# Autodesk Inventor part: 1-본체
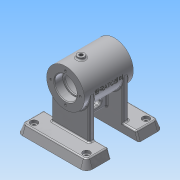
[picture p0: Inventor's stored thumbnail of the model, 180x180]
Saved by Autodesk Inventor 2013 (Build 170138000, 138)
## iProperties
Created: 2016-07
Part Number: 1-본체
Material: 알루미늄 6061
Document SubType Name: Modeling
Designer: Administrator
Density: 2.71 g/cm^3
Mass: 500.735 g
Surface Area: 535.201 cm^2
Volume: 184.773 cm^3
Author: Administrator
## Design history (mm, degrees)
sketch "스케치1"
  geometry: C1 r 27 at (0, 70); 1 further point
  constraints: 1 centre point, 1 vertical alignment
  dimensions: "d0" = 54 diameter of C1; "d1" = 70 distance of point (0, 0) C1.centre
extrude "돌출1" new body sketch "스케치1" stored distance "d2" = 70; taper "d3" = 0 deg
node "작업 평면1"
sketch "스케치2"
  geometry: L1 (-50, 0)-(50, 0); L2 (-45.632, 12)-(45.632, 12); L3 (50, 0)-(45.632, 12); L4 (-50, 0)-(-45.632, 12); 2 further points
  constraints: 8 end point, 2 horizontal alignment, 1 horizontal, 1 midpoint, 1 parallel
  dimensions: "d5" = 100 distance of L1.start L1.end; "d7" = 50 distance of point (0, 0) L1.start; "d8" = 12 distance between parallel lines of L1 L2; "d9" = 70 deg angle of L1 L3; "d11" = 70 deg angle of L1 L4
extrude "돌출2" join sketch "스케치2" distance "d12" = 35; taper "d13" = 0 deg
feature "면 기울기2" dims angle "d17" = 20 deg
fillet "모깎기2" dims "d18" = 5, "d19" = 10
fillet "모깎기3" dims "d20" = 10, "d21" = 5
sketch "스케치3"
  geometry: L1 (95.632, -12)-(4.368, -12) reference; L2 (23, -12)-(23, -70); L3 (77, -12)-(77, -70); L4 (8.59, -12)-(91.41, -12) reference; L5 (23, -70)-(77, -70); L6 (77, -12)-(23, -12); A1 r 27 centre (50, -70) between (23, -70) and (77, -70) reference; 1 further point
  constraints: 8 end point, 2 point on circle, 2 point on line, 1 parallel, 1 perpendicular
  dimensions: "d22" = 27 distance from line of point (50, 0) L2; "d23" = 27 distance from line of point (50, 0) L3
extrude "돌출3" join sketch "스케치3" distance "d24" = 8; taper "d25" = 0 deg
sketch "스케치5"
  geometry: L1 (-22, 22)-(-22, 62); L2 (-22, 62)-(22, 62); L3 (22, 62)-(22, 22); L4 (22, 22)-(-22, 22); L5 (-35, 43)-(35, 43) reference; 1 further point
  constraints: 8 end point, 2 parallel, 1 perpendicular, 1 vertical
  dimensions: "d29" = 21 distance between parallel lines of L4 L5; "d30" = 40 distance between parallel lines of L2 L4; "d31" = 22 distance from line of L3 point (0, 0); "d32" = 22 distance from line of point (0, 0) L1
extrude "돌출4" join sketch "스케치5" stored distance "d33" = 8; taper "d34" = 0 deg
sketch "스케치6"
  geometry: L1 (-22, -20)-(-22, 20) reference; L2 (-35.5, 8)-(-35.5, -8); L3 (-28.5, 8)-(-28.5, -8); A1 r 3.5 centre (-32, 8) between (-35.5, 8) and (-28.5, 8); A2 r 3.5 centre (-32, -8) between (-35.5, -8) and (-28.5, -8); 1 further point
  constraints: 4 end point, 4 point on circle, 2 centre point, 2 tangent, 1 parallel, 1 vertical alignment
  dimensions: "d35" = 7 diameter of A1; "d36" = 7 diameter of A2; "d37" = 16 distance of A2.centre A1.centre; "d38" = 32 horizontal distance of A2.centre point (0, 0); "d39" = 8 vertical distance of point (0, 0) A1.centre; "d40" = 16 distance of L3.start L3.end
extrude "돌출5" cut sketch "스케치6" distance "d41" = 20; taper "d42" = 0 deg
node "작업 평면2"
sketch "스케치7"
  geometry: L1 (-27, -35)-(27, -35) reference; C1 r 5 at (0, -13); 1 further point
  constraints: 1 centre point, 1 vertical alignment
  dimensions: "d44" = 10 diameter of C1; "d45" = 22 distance from line of C1.centre L1
extrude "돌출6" join sketch "스케치7" distance "d46" = 20; taper "d47" = 0 deg
sketch "스케치8"
  geometry: L1 (-47.948, 70)-(56.24, 70); L2 (50, 0)-(-50, 0) reference; L3 (0, 70)-(15.898, 44.559); 2 further points
  constraints: 4 end point, 1 horizontal, 1 midpoint, 1 point on line, 1 vertical alignment
  dimensions: "d48" = 70 distance between parallel lines of L2 L1; "d49" = 30 distance of L3.start L3.end; "d50" = 58 deg angle of L1 L3
node "작업 평면3"
sketch "스케치9"
  geometry: C1 r 6 at (0, 0); 2 further points
  constraints: 1 centre point, 1 coincident
  dimensions: "d51" = 12 diameter of C1
extrude "돌출7" join sketch "스케치9" distance "d53" = 20; taper "d54" = 0 deg
sketch "스케치10"
  geometry: C1 r 27 at (0, 0) reference; C2 r 16 at (0, 0); 1 further point
  constraints: 1 centre point, 1 coincident
  dimensions: "d55" = 32 diameter of C2
extrude "돌출8" cut sketch "스케치10" distance "d56" = 12; taper "d57" = 0 deg
sketch "스케치11"
  geometry: C1 r 16 at (0, 0) reference; C2 r 14 at (0, 0); 1 further point
  constraints: 1 centre point, 1 coincident
  dimensions: "d58" = 28 diameter of C2
extrude "돌출9" cut sketch "스케치11" distance "d59" = 2; taper "d60" = 0 deg
sketch "스케치12"
  geometry: C1 r 14 at (0, 0) reference; C2 r 22 at (0, 0); 1 further point
  constraints: 1 centre point, 1 coincident
  dimensions: "d61" = 44 diameter of C2
extrude "돌출10" cut sketch "스케치12" distance "d62" = 42; taper "d63" = 0 deg
sketch "스케치13"
  geometry: L1 (-8.59, 4.078)-(-8.59, 30.632) reference; L2 (82.964, -4.368)-(-0.145, -4.368) reference; L3 (41.41, 118.945)-(41.41, -15.828); 3 further points
  constraints: 2 end point, 1 perpendicular, 1 symmetric about line, 1 vertical alignment
  dimensions: "d64" = 12.5 distance from line of L1 point (3.91, 8.132); "d65" = 12.5 distance from line of point (3.91, 8.132) L2
hole "구멍1" sketch "스케치13" at (3.91, 8.132), (78.91, 8.132) diameter "d66" = 6; stored, may be unused: countersink angle "d70" = 90 deg, drill point angle "d72" = 118 deg; dims "d67" = 6, "d68" = 10, "d69" = 4, "d71" = 8
node "작업 평면4"
sketch "스케치14"
  geometry: L1 (-35, 97)-(-35, 43) reference; 2 further points
  constraints: 1 other
  dimensions: "d74" = 35 distance from line of point (0, 70) L1; "d75" = 70 distance of point (0, 70) point (0, 0)
feature "엠보싱1" sketch "스케치14" dims "d76" = 0.5, "d77" = 0
hole "구멍2" diameter "d80" = 5.188; stored, may be unused: countersink angle "d84" = 90 deg, drill point angle "d86" = 118 deg; dims "d78" = 10, "d79" = 10, "d81" = 30, "d82" = 10, "d83" = 4, "d85" = 30
hole "구멍3" diameter "d89" = 5.188; stored, may be unused: countersink angle "d93" = 90 deg, drill point angle "d95" = 118 deg; dims "d87" = 10, "d88" = 10, "d90" = 30, "d91" = 10, "d92" = 4, "d94" = 30
fillet "모깎기4" dims "d96" = 0.3
fillet "모깎기5" dims "d97" = 2
fillet "모깎기6" dims "d98" = 2
fillet "모깎기7" dims "d99" = 2
fillet "모깎기8" dims "d100" = 2
chamfer "모따기1" distance "d101" = 1; stored, may be unused: second distance "d102" = 2, angle "d103" = 45 deg
fillet "모깎기9" dims "d104" = 2
fillet "모깎기10" dims "d105" = 2
fillet "모깎기11" dims "d106" = 2
fillet "모깎기12" dims "d107" = 2
sketch "스케치16"
  geometry: C1 r 27 at (0, 0) reference; 2 further points
  constraints: 1 vertical alignment
  dimensions: "d108" = 21 distance of C1.centre point (0, 21)
hole "구멍4" sketch "스케치16" at (0, 21) diameter "d109" = 3.242; stored, may be unused: countersink angle "d113" = 90 deg, drill point angle "d115" = 118 deg; dims "d110" = 8, "d111" = 10, "d112" = 4, "d114" = 10
node "솔리드1"
mirror "대칭1"
mirror "대칭2"
mirror "대칭3"
mirror "대칭4"
pattern_circular "원형 패턴1" dims angle "d117" = 360 deg
mirror "대칭5"
other parameters: "d4" = 55, "d73" = 27.5
